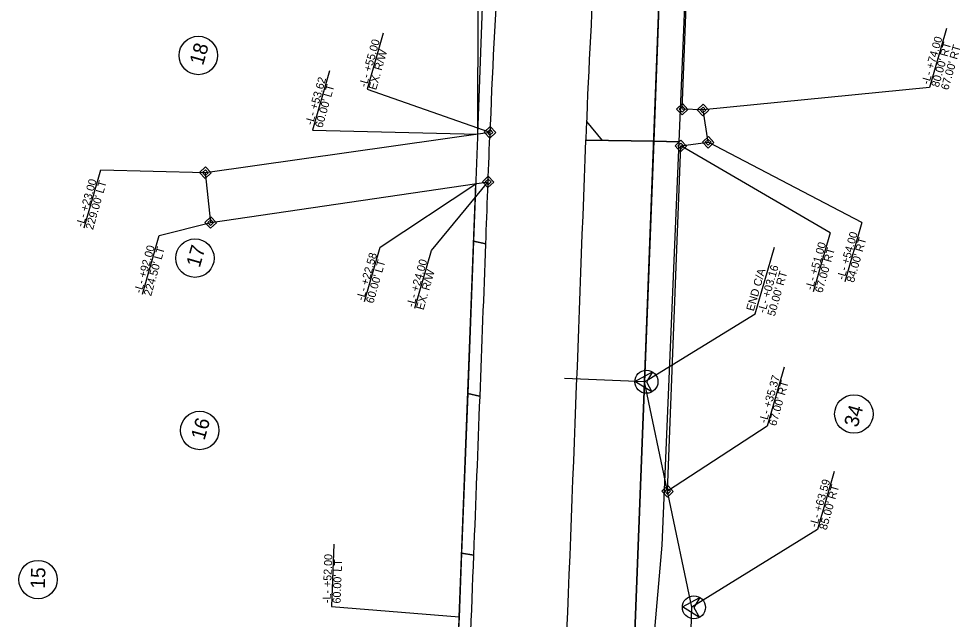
# Model space of a CAD drawing. Extents: x 2097272 to 2098144, y 685104 to 689282.
# Drawn here: x 2097433 to 2098021, y 688071 to 688445 of the extents above; entities that cross this region are included whole.
import ezdxf

# ---------------------------------------------------------------- set-up
doc = ezdxf.new("R2010")
doc.units = 0
for name, color, linetype in [('Prop Easement Construction', 7, 'Continuous'), ('Prop Easement Construction Station Offsets', 7, 'Continuous'), ('Prop Easement Permanent Utility', 7, 'Continuous'), ('Prop Easement Permanent Utility Station Offsets', 7, 'Continuous'), ('Prop Parcel Number CELL', 7, 'Continuous'), ('Prop ROW CA Lines', 7, 'Continuous'), ('Prop ROW Marker CELL', 7, 'Continuous'), ('Prop ROW Permanent Easement CELL', 7, 'Continuous'), ('Prop ROW RW Lines', 7, 'Continuous'), ('Prop ROW Station Offsets', 7, 'Continuous'), ('Scratch_Level_3', 7, 'Continuous'), ('Scratch_Level_6', 7, 'Continuous')]:
    doc.layers.add(name, color=color, linetype=linetype)

msp = doc.modelspace()

# ---------------------------------------------------------------- linework, layer by layer
at = {"layer": 'Prop Easement Construction'}
for p, q in [((2097719.27, 688373.62), (2097724.68, 688514.75)), ((2097707.71, 688072.22), (2097718.08, 688342.6)), ((2097704.34, 687932.25), (2097707.71, 688072.22))]:
    msp.add_line(p, q, dxfattribs=at)
at = {"layer": 'Prop Easement Construction Station Offsets'}
for p, q in [((2097626.69, 688413.01), (2097616.08, 688375.96)), ((2097616.08, 688375.96), (2097719.27, 688373.62)), ((2097658.37, 688302.95), (2097718.08, 688342.6)), ((2097648.68, 688269.1), (2097658.37, 688302.95)), ((2097629.4, 688117.65), (2097627.91, 688078.81)), ((2097627.91, 688078.81), (2097707.71, 688072.22))]:
    msp.add_line(p, q, dxfattribs=at)
at = {"layer": 'Prop Easement Permanent Utility'}
for p, q in [((2097846.96, 688389.12), (2097853.42, 688553.17)), ((2097859.95, 688388.62), (2097846.96, 688389.12)), ((2097863.18, 688368.48), (2097859.95, 688388.62)), ((2097549.22, 688349.5), (2097726.91, 688374.71)), ((2097837.81, 688150.66), (2097846.08, 688366.14)), ((2097846.08, 688366.14), (2097863.18, 688368.48)), ((2097552.53, 688318.35), (2097549.22, 688349.5)), ((2097552.53, 688318.35), (2097725.77, 688343.73))]:
    msp.add_line(p, q, dxfattribs=at)
at = {"layer": 'Prop Easement Permanent Utility Station Offsets'}
for p, q in [((2097660.24, 688436.64), (2097650.19, 688401.56)), ((2098011.95, 688439.45), (2098001.39, 688402.57)), ((2097650.19, 688401.56), (2097726.91, 688374.71)), ((2098001.39, 688402.57), (2097859.95, 688388.62)), ((2097939.38, 688311.91), (2097846.08, 688366.14)), ((2097959.12, 688318.34), (2097863.18, 688368.48)), ((2097473.61, 688315.08), (2097483.96, 688351.23)), ((2097483.96, 688351.23), (2097549.22, 688349.5)), ((2097690.33, 688300.97), (2097725.77, 688343.73)), ((2097520.4, 688310.28), (2097552.53, 688318.35)), ((2097959.12, 688318.34), (2097948.56, 688281.46)), ((2097939.38, 688311.91), (2097928.82, 688275.03)), ((2097509.93, 688273.7), (2097520.4, 688310.28)), ((2097680.03, 688265), (2097690.33, 688300.97)), ((2097910.58, 688228.2), (2097900.02, 688191.32)), ((2097900.02, 688191.32), (2097837.81, 688150.66))]:
    msp.add_line(p, q, dxfattribs=at)
at = {"layer": 'Prop Parcel Number CELL'}
for centre in [(2097544.85, 688422.65), (2097542.7, 688296.13), (2097954.15, 688198.85), (2097545.69, 688188.6), (2097444.74, 688095.54)]:
    msp.add_circle(centre, 12, dxfattribs=at)
at = {"layer": 'Prop ROW CA Lines'}
for p, q in [((2097823.42, 688219.05), (2097773.46, 688220.97)), ((2097853.05, 688078.25), (2097823.42, 688219.05)), ((2097851.65, 688041.68), (2097853.05, 688078.25))]:
    msp.add_line(p, q, dxfattribs=at)
at = {"layer": 'Prop ROW Marker CELL'}
for p, q in [((2097846.96, 688389.12), (2097846.96, 688389.12)), ((2097859.95, 688388.62), (2097859.95, 688388.62)), ((2097726.91, 688374.71), (2097726.91, 688374.71)), ((2097846.08, 688366.14), (2097846.08, 688366.14)), ((2097863.18, 688368.48), (2097863.18, 688368.48)), ((2097549.22, 688349.5), (2097549.22, 688349.5)), ((2097725.77, 688343.73), (2097725.77, 688343.73)), ((2097552.53, 688318.35), (2097552.53, 688318.35)), ((2097817.42, 688219.23), (2097828.4, 688225.16)), ((2097828.4, 688225.16), (2097824.62, 688219.02)), ((2097828.04, 688212.67), (2097817.42, 688219.23)), ((2097824.62, 688219.02), (2097828.04, 688212.67)), ((2097837.81, 688150.66), (2097837.81, 688150.66)), ((2097847.05, 688078.42), (2097858.03, 688084.36)), ((2097858.03, 688084.36), (2097854.25, 688078.21)), ((2097857.66, 688071.86), (2097847.05, 688078.42)), ((2097854.25, 688078.21), (2097857.66, 688071.86))]:
    msp.add_line(p, q, dxfattribs=at)
for centre in [(2097824.62, 688219.02), (2097854.25, 688078.21)]:
    msp.add_circle(centre, 7.2, dxfattribs=at)
at = {"layer": 'Prop ROW Permanent Easement CELL'}
for points in [[(2097843.36, 688389.22), (2097847.06, 688392.72), (2097850.55, 688389.01), (2097846.85, 688385.52)], [(2097845.16, 688389.17), (2097847.01, 688390.92), (2097848.76, 688389.07), (2097846.9, 688387.32)], [(2097856.35, 688388.73), (2097860.05, 688392.22), (2097863.54, 688388.52), (2097859.84, 688385.02)], [(2097858.15, 688388.67), (2097860, 688390.42), (2097861.75, 688388.57), (2097859.9, 688386.82)], [(2097723.31, 688374.81), (2097727.02, 688378.31), (2097730.51, 688374.6), (2097726.81, 688371.11)], [(2097725.11, 688374.76), (2097726.96, 688376.51), (2097728.71, 688374.66), (2097726.86, 688372.91)], [(2097859.58, 688368.59), (2097863.28, 688372.08), (2097866.78, 688368.38), (2097863.07, 688364.88)], [(2097861.38, 688368.53), (2097863.23, 688370.28), (2097864.98, 688368.43), (2097863.13, 688366.68)], [(2097842.48, 688366.24), (2097846.18, 688369.73), (2097849.67, 688366.03), (2097845.97, 688362.54)], [(2097844.28, 688366.19), (2097846.13, 688367.93), (2097847.87, 688366.08), (2097846.02, 688364.34)], [(2097545.62, 688349.6), (2097549.32, 688353.1), (2097552.82, 688349.4), (2097549.12, 688345.9)], [(2097547.42, 688349.55), (2097549.27, 688351.3), (2097551.02, 688349.45), (2097549.17, 688347.7)], [(2097722.18, 688343.83), (2097725.88, 688347.33), (2097729.37, 688343.62), (2097725.67, 688340.13)], [(2097723.97, 688343.78), (2097725.83, 688345.53), (2097727.57, 688343.68), (2097725.72, 688341.93)], [(2097548.93, 688318.45), (2097552.63, 688321.95), (2097556.13, 688318.25), (2097552.42, 688314.75)], [(2097550.73, 688318.4), (2097552.58, 688320.15), (2097554.33, 688318.3), (2097552.48, 688316.55)], [(2097834.21, 688150.77), (2097837.92, 688154.26), (2097841.41, 688150.56), (2097837.71, 688147.06)], [(2097836.01, 688150.71), (2097837.86, 688152.46), (2097839.61, 688150.61), (2097837.76, 688148.86)]]:
    msp.add_lwpolyline(points, close=True, dxfattribs=at)
at = {"layer": 'Prop ROW RW Lines'}
msp.add_line((2097823.42, 688219.05), (2097835.21, 688526.47), dxfattribs=at)
at = {"layer": 'Prop ROW Station Offsets'}
for p, q in [((2097892.59, 688261.39), (2097904.51, 688303.03)), ((2097823.42, 688219.05), (2097892.59, 688261.39)), ((2097941.8, 688163.08), (2097931.4, 688126.75)), ((2097931.4, 688126.75), (2097853.05, 688078.25))]:
    msp.add_line(p, q, dxfattribs=at)
at = {"layer": 'Scratch_Level_3'}
for p, q in [((2097829.17, 688369.06), (2097835.21, 688526.47)), ((2097787.21, 688381.36), (2097796.95, 688369.6)), ((2097786.77, 688369.77), (2097829.17, 688369.06)), ((2097829.17, 688369.06), (2097786.77, 688369.77)), ((2097814.67, 687990.72), (2097829.17, 688369.06))]:
    msp.add_line(p, q, dxfattribs=at)
for centre, radius, start, end in [((2101879.05, 688220.48), 4095, 176.30351, 177.90917), ((2013738.87, 691438.31), 84103.89, 357.6520239, 357.9090947), ((2013738.87, 691438.31), 84103.89, 357.9090947, 357.9091727)]:
    msp.add_arc(centre, radius, start, end, dxfattribs=at)
at = {"layer": 'Scratch_Level_6'}
for p, q in [((2097845.06, 688368.79), (2097853.1, 688560.84)), ((2097835.21, 688526.47), (2097829.17, 688369.06)), ((2097719.57, 688515.78), (2097719.2, 688371.69)), ((2097719.2, 688371.69), (2097716.7, 688306.76)), ((2097829.17, 688369.06), (2097814.67, 687990.72)), ((2097845.06, 688368.79), (2097829.17, 688369.06)), ((2097829.17, 688369.06), (2097845.06, 688368.79)), ((2097834.52, 688117.08), (2097845.06, 688368.79)), ((2097716.7, 688306.76), (2097713.06, 688211.62)), ((2097724.34, 688304.99), (2097716.7, 688306.76)), ((2097716.7, 688306.76), (2097724.34, 688304.99)), ((2097713.06, 688211.62), (2097709.23, 688111.95)), ((2097720.42, 688209.91), (2097713.06, 688211.62)), ((2097713.06, 688211.62), (2097720.42, 688209.91)), ((2097720.73, 688209.83), (2097720.42, 688209.91)), ((2097720.42, 688209.91), (2097720.73, 688209.83)), ((2097709.23, 688111.95), (2097707.7, 688071.91)), ((2097716.87, 688110.86), (2097709.23, 688111.95)), ((2097709.23, 688111.95), (2097716.87, 688110.86)), ((2097823.3, 687990.32), (2097834.52, 688117.08)), ((2097707.7, 688071.91), (2097703.11, 688001.47))]:
    msp.add_line(p, q, dxfattribs=at)
for centre, radius, start, end in [((2101879.05, 688220.48), 4155, 176.30351, 177.90917), ((2013738.87, 691438.31), 84043.89, 357.8634062, 357.9091727), ((2013738.87, 691438.31), 84043.89, 357.7984906, 357.8634062), ((2013738.87, 691438.31), 84043.89, 357.7309688, 357.7984906), ((2013738.87, 691438.31), 84043.89, 357.6560471, 357.7309688)]:
    msp.add_arc(centre, radius, start, end, dxfattribs=at)

# ---------------------------------------------------------------- texts
at = {"layer": 'Prop Easement Construction Station Offsets'}
for s, rotation, p in [('-L- +53.62', 74.02589, (2097616.25, 688378.82)), ("60.00' LT", 74.02589, (2097622.26, 688377.1)), ('-L- +22.58', 74.02589, (2097648.08, 688269.27)), ("60.00' LT", 74.02589, (2097654.09, 688267.55)), ('-L- +52.00', 87.8037, (2097627.36, 688080.76)), ("60.00' LT", 87.8037, (2097633.61, 688080.52))]:
    msp.add_text(s, height=5, rotation=rotation, dxfattribs=at).set_placement(p)
at = {"layer": 'Prop Easement Permanent Utility Station Offsets'}
for s, p in [('-L- +55.00', (2097649.8, 688402.45)), ('-L- +74.00', (2098001.06, 688404.15)), ("80.00' RT", (2098007.07, 688402.43)), ("67.00' RT", (2098013.08, 688400.71)), ('EX. R/W', (2097655.81, 688400.73)), ('-L- +23.00', (2097473.01, 688315.25)), ("229.00' LT", (2097479.02, 688313.53)), ('-L- +54.00', (2097948.16, 688282.26)), ('-L- +51.00', (2097928.42, 688275.83)), ("84.00' RT", (2097954.16, 688280.54)), ('-L- +92.00', (2097509.33, 688273.87)), ("224.50' LT", (2097515.34, 688272.15)), ("67.00' RT", (2097934.43, 688274.11)), ('-L- +24.00', (2097679.43, 688265.17)), ('EX. R/W', (2097685.44, 688263.45)), ('-L- +35.37', (2097899.57, 688192.78)), ("67.00' RT", (2097905.58, 688191.06))]:
    msp.add_text(s, height=5, rotation=74.02589, dxfattribs=at).set_placement(p)
at = {"layer": 'Prop Parcel Number CELL'}
for s, rotation, p in [('18', 74.02589, (2097547.72, 688416.01)), ('17', 74.02589, (2097545.67, 688289.8)), ('34', 74.02589, (2097956.41, 688190.07)), ('16', 74.02589, (2097548.6, 688182.06)), ('15', 88.33483, (2097449, 688089.68))]:
    msp.add_text(s, height=9, rotation=rotation, dxfattribs=at).set_placement(p)
at = {"layer": 'Prop ROW Station Offsets'}
for s, p in [('END C/A', (2097891.57, 688262.73)), ('-L- +03.16', (2097898.79, 688261.56)), ("50.00' RT", (2097904.74, 688259.55)), ('-L- +63.59', (2097931.07, 688127.85)), ("85.00' RT", (2097937.08, 688126.13))]:
    msp.add_text(s, height=5, rotation=74.02589, dxfattribs=at).set_placement(p)

doc.saveas('drawing.dxf')
